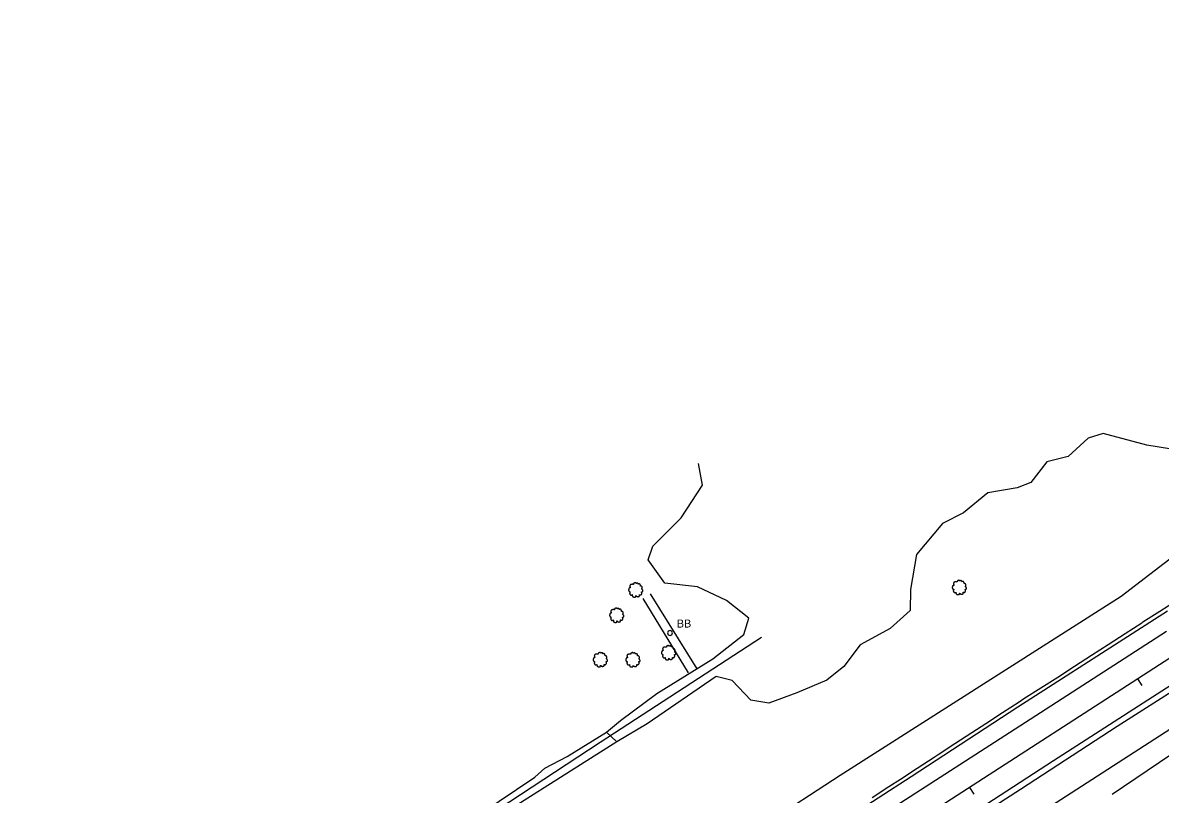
# Model space of a CAD drawing. Extents: x 1901471 to 1963503, y 756461 to 799997.
# Drawn here: x 1922598 to 1923167, y 769131 to 769516 of the extents above; entities that cross this region are included whole.
import ezdxf

# ---------------------------------------------------------------- set-up
doc = ezdxf.new("R2010")
doc.units = 0
for name, color, linetype in [('Default', 7, 'Continuous'), ('RD_DTM_BkLn1', 7, 'Continuous'), ('RD_EX_Bldg', 7, 'Continuous'), ('RD_EX_Fence_Other', 7, 'Continuous'), ('RD_EX_H2O', 7, 'Continuous'), ('RD_EX_Road', 7, 'Continuous'), ('RD_EX_VEG', 7, 'Continuous'), ('RD_HC_Cl', 7, 'Continuous'), ('RD_HC_Data_Tic', 7, 'Continuous')]:
    doc.layers.add(name, color=color, linetype=linetype)

# ---------------------------------------------------------------- blocks, each defined once
blk = doc.blocks.new('T2')
at = {"layer": 'RD_EX_VEG'}
for points in [[(0.05233333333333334, 7.213166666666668), (-0.24750000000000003, 7.238166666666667), (-0.5723333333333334, 7.138166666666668), (-0.8222500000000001, 7.038250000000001), (-1.0471666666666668, 6.963250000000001), (-1.2720833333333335, 6.863250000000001), (-1.5719166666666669, 6.688416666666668), (-1.7968333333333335, 6.488416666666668), (-1.9218333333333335, 6.2385833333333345), (-1.9718333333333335, 6.013666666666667), (-2.0217500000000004, 5.738833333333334), (-2.0217500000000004, 5.563833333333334), (-2.146666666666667, 5.538833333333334), (-2.296666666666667, 5.563833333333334), (-2.5465000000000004, 5.638833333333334), (-2.796416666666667, 5.638833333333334), (-3.0463333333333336, 5.638833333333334), (-3.3961666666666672, 5.613833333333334), (-3.7460000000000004, 5.613833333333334), (-4.020833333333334, 5.563833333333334), (-4.345750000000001, 5.513916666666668), (-4.720583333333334, 5.389000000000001), (-5.0704166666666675, 5.264000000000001), (-5.37025, 5.014083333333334), (-5.620166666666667, 4.539333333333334), (-5.745166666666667, 4.189500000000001), (-5.895083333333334, 3.9395833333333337), (-5.745166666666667, 3.489833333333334), (-5.570166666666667, 3.139916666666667), (-5.545250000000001, 2.9400000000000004), (-5.470250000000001, 2.5152500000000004), (-5.37025, 2.2903333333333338), (-5.245333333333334, 2.0903333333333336), (-5.320250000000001, 2.065416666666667), (-5.695166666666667, 2.015416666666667), (-5.995000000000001, 1.9155000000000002), (-6.419833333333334, 1.6905833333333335), (-6.644750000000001, 1.465666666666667), (-6.744750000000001, 1.1407500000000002), (-6.769666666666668, 0.7909166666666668), (-6.869583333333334, 0.5910833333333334), (-6.944583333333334, 0.3161666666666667), (-6.969583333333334, 0.2411666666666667), (-7.019583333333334, -0.08366666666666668), (-6.9195833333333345, -0.5335000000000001), (-6.894583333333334, -0.8833333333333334), (-6.769666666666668, -1.1082500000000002), (-6.619750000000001, -1.2830833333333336), (-6.444833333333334, -1.5330000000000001), (-6.045000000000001, -1.7579166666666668), (-5.7201666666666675, -1.8579166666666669), (-5.520250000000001, -1.8828333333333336), (-5.695166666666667, -2.382666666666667), (-5.745166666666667, -2.7325000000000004), (-5.870083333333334, -3.132333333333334), (-5.870083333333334, -3.2072500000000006), (-5.920000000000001, -3.682083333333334), (-5.770166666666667, -4.007000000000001), (-5.695166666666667, -4.38175), (-5.520250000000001, -4.606666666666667), (-5.245333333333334, -4.906583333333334), (-4.9205000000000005, -5.131416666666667), (-4.420666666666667, -5.256416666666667), (-4.020833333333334, -5.231416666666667), (-3.4460833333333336, -5.056500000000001), (-3.1962500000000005, -4.9815000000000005), (-3.2212500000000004, -5.156416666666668), (-3.1962500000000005, -5.531333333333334), (-3.1962500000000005, -5.956083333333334), (-3.0463333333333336, -6.280916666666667), (-2.946333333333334, -6.555833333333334), (-2.796416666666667, -6.805750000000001), (-2.4715000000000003, -7.030583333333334), (-2.07175, -7.1055833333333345), (-1.6469166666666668, -7.2555000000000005), (-1.1970833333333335, -7.330500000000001), (-0.6973333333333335, -7.355500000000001), (-0.09758333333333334, -7.205583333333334), (0.17725000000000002, -7.080583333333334), (0.27725000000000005, -6.905666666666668), (0.47716666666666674, -6.530833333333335), (0.4271666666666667, -6.3059166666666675), (0.4521666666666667, -5.706166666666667), (0.5520833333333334, -5.881166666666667), (0.7270833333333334, -6.231000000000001), (1.2268333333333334, -6.530833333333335), (1.626666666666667, -6.705750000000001), (2.101416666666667, -6.8557500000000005), (2.4013333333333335, -6.930666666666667), (2.8760833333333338, -6.8557500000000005), (3.2510000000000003, -6.780750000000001), (3.6257500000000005, -6.655750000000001), (3.9256666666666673, -6.380916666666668), (4.100583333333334, -6.106000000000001), (4.1505833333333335, -5.831166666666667), (4.2255, -5.456333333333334), (4.275500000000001, -5.281416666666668)], [(4.275500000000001, -5.281416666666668), (4.200583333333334, -5.106416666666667), (4.1505833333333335, -4.856583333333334), (4.2255, -4.881583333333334), (4.4004166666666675, -4.931583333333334), (4.675333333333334, -5.056500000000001), (4.900250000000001, -5.131416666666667), (5.225083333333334, -5.106416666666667), (5.500000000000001, -5.006500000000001), (5.949750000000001, -4.731583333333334), (6.224666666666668, -4.256833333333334), (6.499500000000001, -3.8570000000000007), (6.5745000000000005, -3.5321666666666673), (6.524500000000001, -3.3072500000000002), (6.499500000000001, -2.8075000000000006), (6.299583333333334, -2.5575833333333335), (6.249583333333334, -2.432666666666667), (6.1496666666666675, -2.0328333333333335), (6.224666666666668, -1.9828333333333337), (6.499500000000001, -1.9328333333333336), (6.874333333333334, -1.8079166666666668), (7.149250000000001, -1.6830000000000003), (7.374166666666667, -1.5080000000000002), (7.449083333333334, -1.2830833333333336), (7.424166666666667, -0.8833333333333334), (7.4740833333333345, -0.48350000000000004), (7.399166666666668, -0.3335), (7.299166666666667, -0.1836666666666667), (7.224166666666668, 0.016333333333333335), (7.074250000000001, 0.16616666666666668), (6.974333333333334, 0.3161666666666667), (6.874333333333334, 0.41608333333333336), (6.749416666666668, 0.5660833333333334), (6.5745000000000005, 0.6910000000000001), (6.424583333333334, 0.7410000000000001), (6.374583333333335, 0.8909166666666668), (6.524500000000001, 1.0908333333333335), (6.5745000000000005, 1.1907500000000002), (6.599416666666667, 1.4156666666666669), (6.824416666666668, 1.7655000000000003), (6.874333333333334, 2.1653333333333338), (6.824416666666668, 2.590166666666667), (6.774416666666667, 2.8650833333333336), (6.624416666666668, 3.139916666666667), (6.424583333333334, 3.3898333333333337), (6.299583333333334, 3.5647500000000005), (6.124666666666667, 3.689666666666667), (5.799833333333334, 3.814666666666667), (5.549916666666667, 3.864583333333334), (5.200083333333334, 3.864583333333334), (5.000166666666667, 3.9145833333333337), (5.025166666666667, 3.964583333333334), (5.025166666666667, 4.1145000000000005), (5.025166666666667, 4.389416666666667), (4.950166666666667, 4.839166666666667), (4.800250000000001, 5.339), (4.800250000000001, 5.364000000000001), (4.7002500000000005, 5.613833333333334), (4.475416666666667, 5.813750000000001), (4.3005, 5.913666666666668), (4.100583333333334, 6.038666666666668), (3.850666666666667, 6.063666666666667), (3.5508333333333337, 6.063666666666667), (3.2759166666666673, 6.013666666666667), (3.0760000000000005, 5.913666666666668), (2.9010833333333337, 5.788750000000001), (2.8260833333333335, 5.938666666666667), (2.726166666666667, 6.2385833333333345), (2.676166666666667, 6.3885000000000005), (2.52625, 6.563416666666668), (2.301416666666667, 6.7633333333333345), (1.8515000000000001, 6.888250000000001), (1.2268333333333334, 6.813333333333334), (0.9269166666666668, 6.613416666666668), (0.7770000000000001, 6.438500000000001), (0.7270833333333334, 6.563416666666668), (0.5270833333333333, 6.7633333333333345), (0.4271666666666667, 6.938250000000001), (0.25225000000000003, 7.063250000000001), (0.10233333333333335, 7.163166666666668), (0.0023333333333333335, 7.213166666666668)]]:
    blk.add_spline(points, degree=3, dxfattribs=at)
blk = doc.blocks.new('SIGNPOST')
at = {"layer": 'Default'}
for centre, start, end in [((7.776250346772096e-18, 0), 90.00000000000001, 270), ((-7.776250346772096e-18, 0), 270, 90)]:
    blk.add_arc(centre, 0.12700000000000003, start, end, dxfattribs=at)

msp = doc.modelspace()

# ---------------------------------------------------------------- linework, layer by layer
at = {"layer": 'RD_DTM_BkLn1'}
msp.add_lwpolyline([(1923022.9714583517, 769129.4079156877), (1923031.3674089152, 769134.8395851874), (1923037.1240722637, 769138.5637963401), (1923045.4986177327, 769144.0280643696), (1923053.8731632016, 769149.4923323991), (1923055.9639822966, 769150.8565611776), (1923064.3467868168, 769156.3088061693), (1923072.7295913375, 769161.7610511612), (1923079.7008181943, 769166.2951944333), (1923088.0868590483, 769171.7423633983), (1923096.4728999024, 769177.189532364), (1923098.8439188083, 769178.7296322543), (1923107.266763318, 769184.1198224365), (1923115.6896078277, 769189.5100126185), (1923124.1549331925, 769194.9273883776), (1923132.5484895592, 769200.3625819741), (1923140.9420459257, 769205.797775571), (1923149.3356022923, 769211.2329691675), (1923157.7291586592, 769216.6681627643), (1923158.2469099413, 769217.0034292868), (1923166.675740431, 769222.3843200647), (1923175.1045709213, 769227.7652108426)], dxfattribs=at)
at = {"layer": 'RD_EX_Bldg'}
for points in [[(1922931.1500000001, 769191.5400000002), (1922908.5500000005, 769228.7400000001)], [(1922912.0200000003, 769231.06), (1922935.2600000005, 769193.6000000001)]]:
    msp.add_lwpolyline(points, dxfattribs=at)
at = {"layer": 'RD_EX_Fence_Other'}
msp.add_lwpolyline([(1922967.6000000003, 769209.1900000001), (1922887.0100000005, 769156.7400000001), (1922785.0100000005, 769089.9200000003), (1922675.9200000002, 769019.4500000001), (1922577.7100000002, 768957.3), (1922554.8100000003, 768942.1100000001), (1922398.1200000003, 768841.3500000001), (1922136.4000000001, 768671.4500000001), (1922022.2600000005, 768597.4900000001), (1921921.3400000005, 768533.3400000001), (1921849.4700000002, 768487.5100000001), (1921731.8100000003, 768415.2100000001), (1921706.2500000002, 768398.8400000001)], dxfattribs=at)
at = {"layer": 'RD_EX_H2O'}
for points in [[(1923142.9000000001, 769130.9800000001), (1923195.89, 769166.8400000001), (1923267.6500000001, 769212.7000000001), (1923332.7800000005, 769253.6600000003), (1923402.7200000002, 769300.4300000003), (1923473.7900000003, 769345.2100000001), (1923537.2100000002, 769387.1800000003), (1923599.8700000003, 769426.6300000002), (1923671.5700000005, 769470.7500000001), (1923697.8800000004, 769488.6100000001), (1923713.5400000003, 769498.9500000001)], [(1922295.7600000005, 768685.9700000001), (1922365.4800000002, 768728.0900000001), (1922424.6600000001, 768763.56), (1922493.0200000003, 768807.8700000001), (1922562.3800000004, 768852.5200000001), (1922611.0700000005, 768884.1000000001), (1922697.3600000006, 768940.0100000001), (1922781.5700000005, 768995.2400000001), (1922863.4400000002, 769048.5000000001), (1922931.3100000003, 769091.2800000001), (1923007.0400000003, 769140.4600000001), (1923084.0900000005, 769189.5900000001), (1923147.4100000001, 769229.9000000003), (1923168.9200000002, 769246.3700000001), (1923191.5700000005, 769263.6800000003), (1923207.1900000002, 769278.6500000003), (1923216.2300000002, 769292.1800000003), (1923221.4300000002, 769304.0300000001), (1923224.9000000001, 769311.6800000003), (1923226.4800000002, 769317.2300000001), (1923228.4300000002, 769331.6800000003)]]:
    msp.add_lwpolyline(points, dxfattribs=at)
at = {"layer": 'RD_EX_Road'}
for points in [[(1923170.6300000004, 769222.4900000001), (1923095.8100000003, 769174.4700000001), (1923042.4800000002, 769139.6500000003), (1922992.9100000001, 769107.6900000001), (1922946.4300000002, 769077.55), (1922908.2100000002, 769052.7000000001), (1922867.3100000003, 769026.1400000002), (1922832.6700000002, 769003.83), (1922794.4200000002, 768979.1900000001), (1922762.1100000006, 768958.2900000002), (1922726.8400000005, 768935.4400000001), (1922688.6700000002, 768910.7200000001), (1922628.8100000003, 768872.0900000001), (1922577.2500000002, 768839.08)], [(1923170.1100000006, 769212.2000000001), (1923096.7300000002, 769164.9800000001), (1923032.2100000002, 769123.3500000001), (1922973.3400000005, 769085.2100000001), (1922919.7000000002, 769050.6300000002), (1922869.6100000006, 769018.2400000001), (1922799.3600000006, 768972.7900000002), (1922737.1000000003, 768932.4800000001), (1922678.3800000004, 768894.5000000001), (1922633.6500000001, 768865.4400000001), (1922589.14, 768836.82), (1922506.0900000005, 768783.1900000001), (1922448.0900000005, 768745.8700000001), (1922385.0000000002, 768705.0200000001), (1922327.6700000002, 768667.8900000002), (1922268.5900000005, 768629.7100000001), (1922211.8000000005, 768593.1100000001), (1922156.7400000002, 768557.6500000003), (1922090.0800000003, 768514.7400000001), (1922045.5200000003, 768486.05), (1921991.7500000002, 768451.55)], [(1922030.7400000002, 768448.7900000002), (1922090.39, 768487.0400000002), (1922138.8400000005, 768518.2200000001), (1922194.6100000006, 768554.3800000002), (1922257.2900000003, 768594.6500000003), (1922317.6000000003, 768633.6600000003), (1922381.7900000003, 768675.1900000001), (1922446.5300000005, 768716.8800000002), (1922515.2300000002, 768761.1100000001), (1922595.7800000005, 768813.2500000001), (1922647.4200000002, 768846.3700000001), (1922696.5600000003, 768878.3400000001), (1922749.8800000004, 768912.7400000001), (1922817.7900000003, 768956.7300000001), (1922888.8400000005, 769002.3500000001), (1922957.3800000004, 769046.8), (1923036.9100000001, 769098.0900000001), (1923113.5800000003, 769147.8700000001), (1923186.3400000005, 769194.6800000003)], [(1922540.0100000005, 768773.31), (1922600.0400000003, 768812.1700000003), (1922649.4600000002, 768843.8), (1922698.7300000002, 768875.6800000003), (1922746.7300000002, 768906.6900000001), (1922797.3800000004, 768939.2500000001), (1922845.0300000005, 768970.2400000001), (1922894.2100000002, 769001.9100000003), (1922943.5500000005, 769033.7500000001), (1922994.3400000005, 769067.0100000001), (1923051.1700000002, 769103.9000000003), (1923097.0600000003, 769133.5200000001), (1923145.4800000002, 769164.9700000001), (1923197.9900000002, 769198.5100000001)]]:
    msp.add_lwpolyline(points, dxfattribs=at)
at = {"layer": 'RD_EX_VEG'}
for points in [[(1923182.9000000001, 769301.7300000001), (1923160.2300000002, 769305.2600000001), (1923138.4700000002, 769311.0900000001), (1923130.8700000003, 769308.9000000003), (1923120.9100000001, 769299.6800000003), (1923110.3200000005, 769297.06), (1923102.2500000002, 769286.6300000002), (1923095.3700000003, 769283.9500000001), (1923080.8000000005, 769281.5000000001), (1923068.6700000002, 769271.6100000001), (1923058.0400000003, 769266.1300000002), (1923045.1600000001, 769250.6600000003), (1923042.2000000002, 769233.1800000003), (1923041.9200000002, 769222.7800000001), (1923032.0400000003, 769213.7000000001), (1923016.9400000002, 769205.6300000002), (1923008.8500000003, 769194.7200000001), (1923000.3000000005, 769187.8900000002), (1922985.4000000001, 769181.7000000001), (1922971.3300000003, 769176.3900000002), (1922962.3700000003, 769177.9900000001), (1922953.0300000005, 769187.8500000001), (1922945.0700000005, 769189.7200000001), (1922910.5500000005, 769166.2100000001), (1922895.4100000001, 769157.1900000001), (1922890.2500000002, 769161.9000000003), (1922897.2100000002, 769167.7700000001), (1922915.3600000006, 769181.2700000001), (1922943.3000000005, 769198.6300000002), (1922958.8400000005, 769210.7900000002), (1922961.2700000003, 769218.9800000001), (1922950.0900000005, 769227.7000000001), (1922935.6200000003, 769234.5000000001), (1922919.3200000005, 769236.4800000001), (1922911.0000000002, 769248.1000000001), (1922913.3700000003, 769254.8600000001), (1922927.5300000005, 769269.05), (1922938.1800000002, 769285.3), (1922936.1200000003, 769296.1200000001)], [(1922623.2800000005, 768994.0100000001), (1922641.89, 769001.6800000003), (1922711.2300000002, 769044.9600000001), (1922782.5400000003, 769091.2300000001), (1922854.4400000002, 769139.4800000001), (1922859.4300000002, 769144.0100000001), (1922870.5500000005, 769149.8500000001), (1922890.2500000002, 769161.9000000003)], [(1922895.4100000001, 769157.1900000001), (1922830.8200000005, 769116.3400000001), (1922747.2500000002, 769063.3), (1922679.14, 769018.7000000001), (1922634.0300000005, 768989.2800000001), (1922625.0000000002, 768985.7900000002)]]:
    msp.add_lwpolyline(points, dxfattribs=at)
at = {"layer": 'RD_HC_Cl'}
for p, q in [((1926729.5176193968, 771495.9286460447), (1917217.2707724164, 765354.9153898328)), ((1926745.7566169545, 771470.7766377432), (1917232.2344163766, 765328.8252854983))]:
    msp.add_line(p, q, dxfattribs=at)
at = {"layer": 'RD_HC_Data_Tic'}
for p, q in [((1923155.5941308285, 769188.638699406), (1923157.763655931, 769185.2781695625)), ((1923071.5808847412, 769134.4005718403), (1923073.7504098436, 769131.0400419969))]:
    msp.add_line(p, q, dxfattribs=at)

# ---------------------------------------------------------------- block references
at = {"layer": 'RD_EX_Bldg', "xscale": 9.84251968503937, "yscale": 9.84251968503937}
msp.add_blockref('SIGNPOST', (1922921.9400000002, 769211.5100000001), dxfattribs=at)
at = {"layer": 'RD_EX_VEG', "xscale": 0.4921259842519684, "yscale": 0.4921259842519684}
for p in [(1922904.6800000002, 769233.05), (1923066.4400000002, 769234.2800000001), (1922895.1900000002, 769220.4000000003), (1922921.1200000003, 769201.6900000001), (1922886.9900000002, 769198.2100000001), (1922903.2900000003, 769198.1600000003)]:
    msp.add_blockref('T2', p, dxfattribs=at)

# ---------------------------------------------------------------- texts
at = {"layer": 'RD_EX_Road'}
msp.add_text('BB', height=4.000000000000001, dxfattribs=at).set_placement((1922925.4000000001, 769214.2400000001))

doc.saveas('drawing.dxf')
